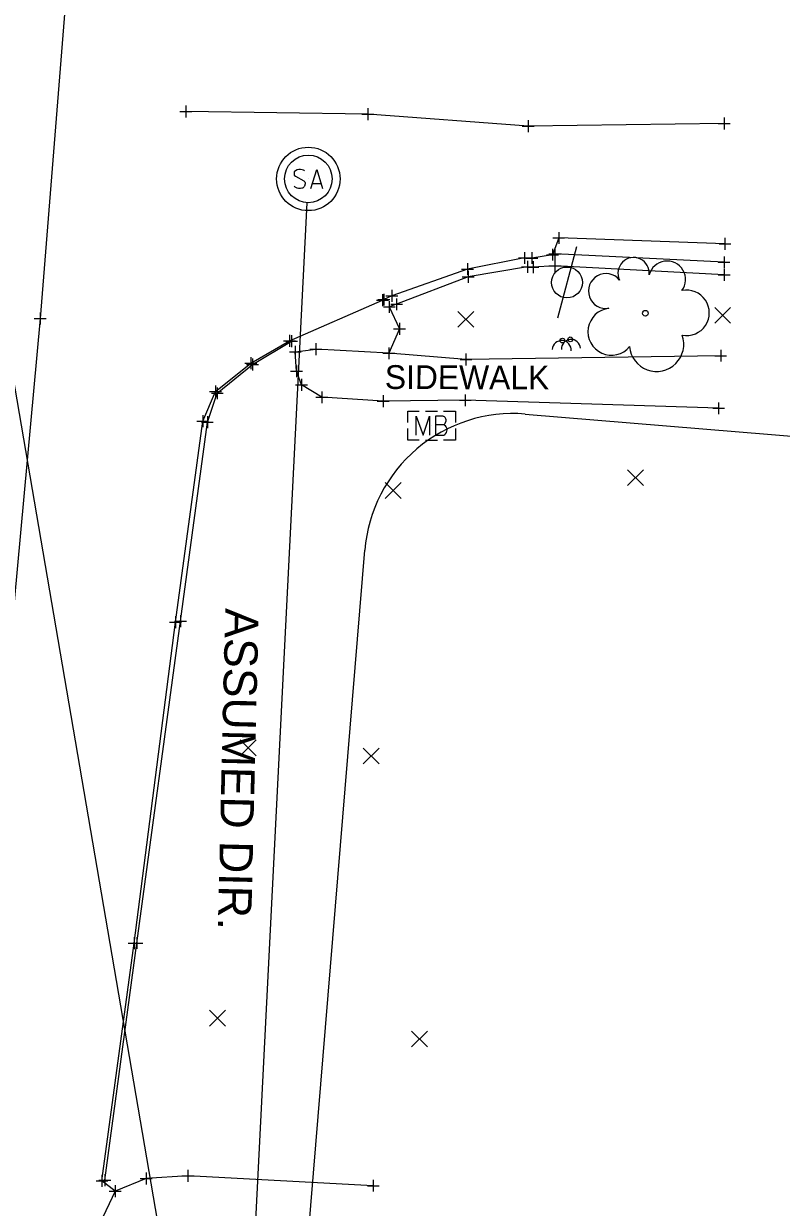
# Model space of a CAD drawing. Extents: x 1380550 to 1381945, y 468927 to 470496.
# Drawn here: x 1381528.9 to 1381592.6, y 469059.1 to 469158.5 of the extents above; entities that cross this region are included whole.
import ezdxf

# ---------------------------------------------------------------- set-up
doc = ezdxf.new("R2010")
doc.units = 0
for name, color, linetype in [('DR_X_Storm_Sewer', 7, 'Continuous'), ('DR_X_Text', 7, 'Continuous'), ('GK_Drainage_Nodes', 7, 'Continuous'), ('PV_X_COP', 7, 'Continuous'), ('PV_X_Curb', 7, 'Continuous'), ('PV_X_EOP', 7, 'Continuous'), ('PV_X_Walk', 7, 'Continuous'), ('RD_X_Cells', 7, 'Continuous'), ('RD_X_Text', 7, 'Continuous'), ('RW_X_Esmt_General', 7, 'Continuous'), ('SV_X_Random_Point', 7, 'Continuous'), ('SV_X_Shot_Marker', 7, 'Continuous'), ('UT_X_Electric', 7, 'Continuous'), ('UT_X_Misc_Cells', 7, 'Continuous'), ('UT_X_Sanitary_Cells', 7, 'Continuous'), ('UT_X_Telecom', 7, 'Continuous'), ('UT_X_Unknown_Cells', 7, 'Continuous'), ('VG_X_Cells', 7, 'Continuous')]:
    doc.layers.add(name, color=color, linetype=linetype)

msp = doc.modelspace()

# ---------------------------------------------------------------- linework, layer by layer
at = {"layer": 'DR_X_Storm_Sewer'}
msp.add_line((1381547.665, 469042.333), (1381552.759, 469143.476), dxfattribs=at)
at = {"layer": 'GK_Drainage_Nodes'}
for p, q in [((1381552.86, 469147.474), (1381552.86, 469147.474)), ((1381552.86, 469145.474), (1381552.86, 469145.474)), ((1381552.86, 469145.474), (1381552.86, 469145.474)), ((1381552.86, 469145.474), (1381552.86, 469145.474)), ((1381552.86, 469143.474), (1381552.86, 469143.474))]:
    msp.add_line(p, q, dxfattribs=at)
msp.add_circle((1381552.86, 469145.474), 2, dxfattribs=at)
at = {"layer": 'PV_X_COP'}
for points in [[(1381585.986, 469815.579), (1381581.288, 469760.779), (1381580.3, 469747.86), (1381578.724, 469729.445), (1381576.782, 469708.953), (1381575.288, 469689.792), (1381572.756, 469657.561), (1381569.364, 469615.703), (1381565.36, 469567.235), (1381561.161, 469537.516), (1381558.939, 469486.814), (1381555.385, 469442.034), (1381550.974, 469391.016), (1381547.282, 469345.901), (1381541.953, 469289.547), (1381537.187, 469231.269), (1381533.052, 469168.087), (1381530.317, 469133.741), (1381523.968, 469065.081), (1381520.119, 469021.37), (1381518.183, 469001.306)], [(1381587.818, 469150.124), (1381571.348, 469149.904), (1381557.859, 469150.909), (1381542.564, 469151.138)]]:
    msp.add_lwpolyline(points, dxfattribs=at)
at = {"layer": 'PV_X_Curb'}
for points in [[(1381587.812, 469138.466), (1381573.591, 469139.185), (1381573.393, 469139.107)], [(1381587.828, 469137.41), (1381573.578, 469138.171), (1381571.753, 469138.061), (1381571.295, 469138.094), (1381566.299, 469137.247), (1381560.284, 469134.94), (1381559.669, 469134.714)]]:
    msp.add_lwpolyline(points, dxfattribs=at)
at = {"layer": 'PV_X_EOP'}
for points in [[(1381587.891, 469140.014), (1381573.909, 469140.511), (1381573.393, 469139.107), (1381571.66, 469138.829), (1381571.03, 469138.831), (1381566.24, 469137.904), (1381559.875, 469135.65), (1381559.212, 469135.332)], [(1381558.323, 469060.888), (1381542.737, 469061.712), (1381539.218, 469061.498), (1381536.628, 469060.419), (1381535.511, 469061.291), (1381538.224, 469081.257), (1381541.702, 469108.24), (1381543.981, 469125.117), (1381545.062, 469127.608), (1381548.027, 469130.001), (1381551.277, 469131.879), (1381559.092, 469135.278)], [(1381559.669, 469134.714), (1381560.522, 469132.872), (1381559.627, 469130.822), (1381553.479, 469131.179)], [(1381535.753, 469061.359), (1381538.437, 469081.275), (1381542.11, 469108.32), (1381544.37, 469125.029), (1381545.209, 469127.461), (1381548.176, 469129.877), (1381551.456, 469131.851)], [(1381587.359, 469126.202), (1381566.057, 469126.873), (1381559.145, 469126.794), (1381553.992, 469127.124), (1381552.293, 469128.183), (1381551.861, 469129.31), (1381551.767, 469130.94), (1381553.479, 469131.179)], [(1381536.628, 469060.419), (1381535.328, 469057.717), (1381532.592, 469035.004), (1381532.732, 469034.306)]]:
    msp.add_lwpolyline(points, dxfattribs=at)
at = {"layer": 'PV_X_Walk'}
for points in [[(1381587.359, 469126.202), (1381566.057, 469126.873), (1381559.145, 469126.794), (1381553.992, 469127.124), (1381552.293, 469128.183), (1381551.861, 469129.31), (1381551.767, 469130.94), (1381553.479, 469131.179)], [(1381587.531, 469130.624), (1381566.113, 469130.294), (1381559.627, 469130.822), (1381553.479, 469131.179)]]:
    msp.add_lwpolyline(points, dxfattribs=at)
at = {"layer": 'RD_X_Cells'}
for p, q in [((1381562.71, 469125.969), (1381563.712, 469125.969)), ((1381563.222, 469124.747), (1381563.222, 469124.747)), ((1381562.71, 469123.526), (1381563.712, 469123.526))]:
    msp.add_line(p, q, dxfattribs=at)
for points in [[(1381561.222, 469124.999), (1381561.222, 469125.969), (1381562.192, 469125.969)], [(1381561.926, 469123.947), (1381561.926, 469125.547), (1381562.505, 469123.947), (1381563.059, 469125.547), (1381563.059, 469123.947)], [(1381564.244, 469124.817), (1381564.307, 469124.88), (1381564.345, 469124.918), (1381564.37, 469124.955), (1381564.382, 469124.98), (1381564.407, 469125.031), (1381564.42, 469125.069), (1381564.445, 469125.157), (1381564.445, 469125.195), (1381564.445, 469125.245), (1381564.433, 469125.321), (1381564.407, 469125.384), (1381564.37, 469125.434), (1381564.307, 469125.484), (1381564.256, 469125.51), (1381564.231, 469125.522), (1381564.168, 469125.547), (1381563.551, 469125.547), (1381563.551, 469123.947), (1381564.244, 469123.947), (1381564.332, 469123.998), (1381564.407, 469124.061), (1381564.47, 469124.162), (1381564.508, 469124.275), (1381564.521, 469124.388), (1381564.521, 469124.464), (1381564.496, 469124.54), (1381564.445, 469124.653), (1381564.382, 469124.728), (1381564.244, 469124.817), (1381563.551, 469124.817)], [(1381564.229, 469125.969), (1381565.222, 469125.969), (1381565.222, 469124.999)], [(1381562.192, 469123.526), (1381561.222, 469123.526), (1381561.222, 469124.496)], [(1381565.222, 469124.496), (1381565.222, 469123.526), (1381564.229, 469123.526)]]:
    msp.add_lwpolyline(points, dxfattribs=at)
at = {"layer": 'RW_X_Esmt_General'}
for p, q in [((1381571.101, 469125.715), (1381598.876, 469123.42)), ((1381550.441, 469027.475), (1381557.614, 469114.287))]:
    msp.add_line(p, q, dxfattribs=at)
msp.add_arc((1381570.071, 469113.258), 12.5, 85.27609, 175.27609, dxfattribs=at)
at = {"layer": 'SV_X_Random_Point'}
for p, q in [((1381565.433, 469133.008), (1381566.767, 469134.343)), ((1381565.433, 469134.343), (1381566.767, 469133.008)), ((1381587.033, 469133.342), (1381588.367, 469134.677)), ((1381587.033, 469134.677), (1381588.367, 469133.342)), ((1381579.697, 469119.709), (1381581.031, 469121.044)), ((1381579.697, 469121.044), (1381581.031, 469119.709)), ((1381559.325, 469118.625), (1381560.659, 469119.96)), ((1381559.325, 469119.96), (1381560.659, 469118.625)), ((1381547.143, 469097.003), (1381548.477, 469098.338)), ((1381547.143, 469098.338), (1381548.477, 469097.003)), ((1381557.485, 469096.319), (1381558.819, 469097.654)), ((1381557.485, 469097.654), (1381558.819, 469096.319)), ((1381544.559, 469074.296), (1381545.893, 469075.631)), ((1381544.559, 469075.631), (1381545.893, 469074.296)), ((1381561.532, 469072.541), (1381562.866, 469073.876)), ((1381561.532, 469073.876), (1381562.866, 469072.541))]:
    msp.add_line(p, q, dxfattribs=at)
at = {"layer": 'SV_X_Shot_Marker'}
for p, q in [((1381542.064, 469151.138), (1381543.064, 469151.138)), ((1381542.564, 469151.638), (1381542.564, 469150.638)), ((1381542.564, 469151.138), (1381542.564, 469151.138)), ((1381557.859, 469151.409), (1381557.859, 469150.409)), ((1381557.359, 469150.909), (1381558.359, 469150.909)), ((1381557.859, 469150.909), (1381557.859, 469150.909)), ((1381571.348, 469150.404), (1381571.348, 469149.404)), ((1381587.318, 469150.124), (1381588.318, 469150.124)), ((1381587.818, 469150.624), (1381587.818, 469149.624)), ((1381587.818, 469150.124), (1381587.818, 469150.124)), ((1381570.848, 469149.904), (1381571.848, 469149.904)), ((1381571.348, 469149.904), (1381571.348, 469149.904)), ((1381573.909, 469141.011), (1381573.909, 469140.011)), ((1381573.409, 469140.511), (1381574.409, 469140.511)), ((1381573.909, 469140.511), (1381573.909, 469140.511)), ((1381587.391, 469140.014), (1381588.391, 469140.014)), ((1381587.891, 469140.514), (1381587.891, 469139.514)), ((1381587.891, 469140.014), (1381587.891, 469140.014)), ((1381571.03, 469139.331), (1381571.03, 469138.331)), ((1381571.03, 469139.331), (1381571.03, 469138.331)), ((1381571.66, 469139.329), (1381571.66, 469138.329)), ((1381572.893, 469139.107), (1381573.893, 469139.107)), ((1381572.893, 469139.107), (1381573.893, 469139.107)), ((1381573.091, 469139.185), (1381574.091, 469139.185)), ((1381573.393, 469139.607), (1381573.393, 469138.607)), ((1381573.393, 469139.607), (1381573.393, 469138.607)), ((1381573.393, 469139.107), (1381573.393, 469139.107)), ((1381573.393, 469139.107), (1381573.393, 469139.107)), ((1381573.591, 469139.685), (1381573.591, 469138.685)), ((1381573.591, 469139.185), (1381573.591, 469139.185)), ((1381566.24, 469138.404), (1381566.24, 469137.404)), ((1381570.53, 469138.831), (1381571.53, 469138.831)), ((1381570.53, 469138.831), (1381571.53, 469138.831)), ((1381570.795, 469138.094), (1381571.795, 469138.094)), ((1381570.795, 469138.094), (1381571.795, 469138.094)), ((1381571.03, 469138.831), (1381571.03, 469138.831)), ((1381571.03, 469138.831), (1381571.03, 469138.831)), ((1381571.16, 469138.829), (1381572.16, 469138.829)), ((1381571.253, 469138.061), (1381572.253, 469138.061)), ((1381571.295, 469138.594), (1381571.295, 469137.594)), ((1381571.295, 469138.594), (1381571.295, 469137.594)), ((1381571.295, 469138.094), (1381571.295, 469138.094)), ((1381571.295, 469138.094), (1381571.295, 469138.094)), ((1381571.66, 469138.829), (1381571.66, 469138.829)), ((1381571.753, 469138.561), (1381571.753, 469137.561)), ((1381571.753, 469138.061), (1381571.753, 469138.061)), ((1381573.078, 469138.171), (1381574.078, 469138.171)), ((1381573.578, 469138.671), (1381573.578, 469137.671)), ((1381573.578, 469138.171), (1381573.578, 469138.171)), ((1381587.312, 469138.466), (1381588.312, 469138.466)), ((1381587.812, 469138.966), (1381587.812, 469137.966)), ((1381587.812, 469138.466), (1381587.812, 469138.466)), ((1381565.74, 469137.904), (1381566.74, 469137.904)), ((1381565.799, 469137.247), (1381566.799, 469137.247)), ((1381566.24, 469137.904), (1381566.24, 469137.904)), ((1381566.299, 469137.747), (1381566.299, 469136.747)), ((1381566.299, 469137.247), (1381566.299, 469137.247)), ((1381587.328, 469137.41), (1381588.328, 469137.41)), ((1381587.828, 469137.91), (1381587.828, 469136.91)), ((1381587.828, 469137.41), (1381587.828, 469137.41)), ((1381559.875, 469136.15), (1381559.875, 469135.15)), ((1381559.875, 469136.15), (1381559.875, 469135.15)), ((1381558.592, 469135.278), (1381559.592, 469135.278)), ((1381558.712, 469135.332), (1381559.712, 469135.332)), ((1381559.092, 469135.778), (1381559.092, 469134.778)), ((1381559.092, 469135.278), (1381559.092, 469135.278)), ((1381559.212, 469135.832), (1381559.212, 469134.832)), ((1381559.212, 469135.332), (1381559.212, 469135.332)), ((1381559.375, 469135.65), (1381560.375, 469135.65)), ((1381559.375, 469135.65), (1381560.375, 469135.65)), ((1381559.669, 469135.214), (1381559.669, 469134.214)), ((1381559.669, 469135.214), (1381559.669, 469134.214)), ((1381559.875, 469135.65), (1381559.875, 469135.65)), ((1381559.875, 469135.65), (1381559.875, 469135.65)), ((1381560.284, 469135.44), (1381560.284, 469134.44)), ((1381560.284, 469135.44), (1381560.284, 469134.44)), ((1381530.317, 469134.241), (1381530.317, 469133.241)), ((1381559.169, 469134.714), (1381560.169, 469134.714)), ((1381559.169, 469134.714), (1381560.169, 469134.714)), ((1381559.669, 469134.714), (1381559.669, 469134.714)), ((1381559.669, 469134.714), (1381559.669, 469134.714)), ((1381559.784, 469134.94), (1381560.784, 469134.94)), ((1381559.784, 469134.94), (1381560.784, 469134.94)), ((1381560.284, 469134.94), (1381560.284, 469134.94)), ((1381560.284, 469134.94), (1381560.284, 469134.94)), ((1381529.817, 469133.741), (1381530.817, 469133.741)), ((1381530.317, 469133.741), (1381530.317, 469133.741)), ((1381560.522, 469133.372), (1381560.522, 469132.372)), ((1381551.277, 469132.379), (1381551.277, 469131.379)), ((1381551.456, 469132.351), (1381551.456, 469131.351)), ((1381560.022, 469132.872), (1381561.022, 469132.872)), ((1381560.522, 469132.872), (1381560.522, 469132.872)), ((1381550.777, 469131.879), (1381551.777, 469131.879)), ((1381550.956, 469131.851), (1381551.956, 469131.851)), ((1381551.277, 469131.879), (1381551.277, 469131.879)), ((1381551.456, 469131.851), (1381551.456, 469131.851)), ((1381551.767, 469131.44), (1381551.767, 469130.44)), ((1381551.767, 469131.44), (1381551.767, 469130.44)), ((1381552.979, 469131.179), (1381553.979, 469131.179)), ((1381552.979, 469131.179), (1381553.979, 469131.179)), ((1381552.979, 469131.179), (1381553.979, 469131.179)), ((1381552.979, 469131.179), (1381553.979, 469131.179)), ((1381553.479, 469131.679), (1381553.479, 469130.679)), ((1381553.479, 469131.679), (1381553.479, 469130.679)), ((1381553.479, 469131.679), (1381553.479, 469130.679)), ((1381553.479, 469131.679), (1381553.479, 469130.679)), ((1381553.479, 469131.179), (1381553.479, 469131.179)), ((1381553.479, 469131.179), (1381553.479, 469131.179)), ((1381553.479, 469131.179), (1381553.479, 469131.179)), ((1381553.479, 469131.179), (1381553.479, 469131.179)), ((1381559.627, 469131.322), (1381559.627, 469130.322)), ((1381559.627, 469131.322), (1381559.627, 469130.322)), ((1381587.531, 469131.124), (1381587.531, 469130.124)), ((1381548.027, 469130.501), (1381548.027, 469129.501)), ((1381548.176, 469130.377), (1381548.176, 469129.377)), ((1381551.267, 469130.94), (1381552.267, 469130.94)), ((1381551.267, 469130.94), (1381552.267, 469130.94)), ((1381551.767, 469130.94), (1381551.767, 469130.94)), ((1381551.767, 469130.94), (1381551.767, 469130.94)), ((1381559.127, 469130.822), (1381560.127, 469130.822)), ((1381559.127, 469130.822), (1381560.127, 469130.822)), ((1381559.627, 469130.822), (1381559.627, 469130.822)), ((1381559.627, 469130.822), (1381559.627, 469130.822)), ((1381565.613, 469130.294), (1381566.613, 469130.294)), ((1381566.113, 469130.794), (1381566.113, 469129.794)), ((1381566.113, 469130.294), (1381566.113, 469130.294)), ((1381587.031, 469130.624), (1381588.031, 469130.624)), ((1381587.531, 469130.624), (1381587.531, 469130.624)), ((1381547.527, 469130.001), (1381548.527, 469130.001)), ((1381547.676, 469129.877), (1381548.676, 469129.877)), ((1381548.027, 469130.001), (1381548.027, 469130.001)), ((1381548.176, 469129.877), (1381548.176, 469129.877)), ((1381551.361, 469129.31), (1381552.361, 469129.31)), ((1381551.361, 469129.31), (1381552.361, 469129.31)), ((1381551.861, 469129.81), (1381551.861, 469128.81)), ((1381551.861, 469129.81), (1381551.861, 469128.81)), ((1381551.861, 469129.31), (1381551.861, 469129.31)), ((1381551.861, 469129.31), (1381551.861, 469129.31)), ((1381545.062, 469128.108), (1381545.062, 469127.108)), ((1381551.793, 469128.183), (1381552.793, 469128.183)), ((1381551.793, 469128.183), (1381552.793, 469128.183)), ((1381552.293, 469128.683), (1381552.293, 469127.683)), ((1381552.293, 469128.683), (1381552.293, 469127.683)), ((1381552.293, 469128.183), (1381552.293, 469128.183)), ((1381552.293, 469128.183), (1381552.293, 469128.183)), ((1381544.562, 469127.608), (1381545.562, 469127.608)), ((1381544.709, 469127.461), (1381545.709, 469127.461)), ((1381545.062, 469127.608), (1381545.062, 469127.608)), ((1381545.209, 469127.961), (1381545.209, 469126.961)), ((1381545.209, 469127.461), (1381545.209, 469127.461)), ((1381553.492, 469127.124), (1381554.492, 469127.124)), ((1381553.492, 469127.124), (1381554.492, 469127.124)), ((1381553.992, 469127.624), (1381553.992, 469126.624)), ((1381553.992, 469127.624), (1381553.992, 469126.624)), ((1381553.992, 469127.124), (1381553.992, 469127.124)), ((1381553.992, 469127.124), (1381553.992, 469127.124)), ((1381559.145, 469127.294), (1381559.145, 469126.294)), ((1381559.145, 469127.294), (1381559.145, 469126.294)), ((1381566.057, 469127.373), (1381566.057, 469126.373)), ((1381566.057, 469127.373), (1381566.057, 469126.373)), ((1381558.645, 469126.794), (1381559.645, 469126.794)), ((1381558.645, 469126.794), (1381559.645, 469126.794)), ((1381559.145, 469126.794), (1381559.145, 469126.794)), ((1381559.145, 469126.794), (1381559.145, 469126.794)), ((1381565.557, 469126.873), (1381566.557, 469126.873)), ((1381565.557, 469126.873), (1381566.557, 469126.873)), ((1381566.057, 469126.873), (1381566.057, 469126.873)), ((1381566.057, 469126.873), (1381566.057, 469126.873)), ((1381586.859, 469126.202), (1381587.859, 469126.202)), ((1381586.859, 469126.202), (1381587.859, 469126.202)), ((1381587.359, 469126.702), (1381587.359, 469125.702)), ((1381587.359, 469126.702), (1381587.359, 469125.702)), ((1381587.359, 469126.202), (1381587.359, 469126.202)), ((1381587.359, 469126.202), (1381587.359, 469126.202)), ((1381543.481, 469125.117), (1381544.481, 469125.117)), ((1381543.981, 469125.617), (1381543.981, 469124.617)), ((1381543.981, 469125.117), (1381543.981, 469125.117)), ((1381544.37, 469125.529), (1381544.37, 469124.529)), ((1381543.87, 469125.029), (1381544.87, 469125.029)), ((1381544.37, 469125.029), (1381544.37, 469125.029)), ((1381541.202, 469108.24), (1381542.202, 469108.24)), ((1381541.61, 469108.32), (1381542.61, 469108.32)), ((1381541.702, 469108.74), (1381541.702, 469107.74)), ((1381541.702, 469108.24), (1381541.702, 469108.24)), ((1381542.11, 469108.82), (1381542.11, 469107.82)), ((1381542.11, 469108.32), (1381542.11, 469108.32)), ((1381538.224, 469081.757), (1381538.224, 469080.757)), ((1381538.437, 469081.775), (1381538.437, 469080.775)), ((1381537.724, 469081.257), (1381538.724, 469081.257)), ((1381537.937, 469081.275), (1381538.937, 469081.275)), ((1381538.224, 469081.257), (1381538.224, 469081.257)), ((1381538.437, 469081.275), (1381538.437, 469081.275)), ((1381535.511, 469061.791), (1381535.511, 469060.791)), ((1381535.753, 469061.859), (1381535.753, 469060.859)), ((1381538.718, 469061.498), (1381539.718, 469061.498)), ((1381539.218, 469061.998), (1381539.218, 469060.998)), ((1381539.218, 469061.498), (1381539.218, 469061.498)), ((1381542.237, 469061.712), (1381543.237, 469061.712)), ((1381542.737, 469062.212), (1381542.737, 469061.212)), ((1381542.737, 469061.712), (1381542.737, 469061.712)), ((1381535.011, 469061.291), (1381536.011, 469061.291)), ((1381535.253, 469061.359), (1381536.253, 469061.359)), ((1381535.511, 469061.291), (1381535.511, 469061.291)), ((1381535.753, 469061.359), (1381535.753, 469061.359)), ((1381536.628, 469060.919), (1381536.628, 469059.919)), ((1381536.628, 469060.919), (1381536.628, 469059.919)), ((1381557.823, 469060.888), (1381558.823, 469060.888)), ((1381558.323, 469061.388), (1381558.323, 469060.388)), ((1381558.323, 469060.888), (1381558.323, 469060.888)), ((1381536.128, 469060.419), (1381537.128, 469060.419)), ((1381536.128, 469060.419), (1381537.128, 469060.419)), ((1381536.628, 469060.419), (1381536.628, 469060.419)), ((1381536.628, 469060.419), (1381536.628, 469060.419))]:
    msp.add_line(p, q, dxfattribs=at)
at = {"layer": 'UT_X_Electric'}
msp.add_lwpolyline([(1381665.562, 470247.404), (1381595.795, 470220.833), (1381581.264, 470018.199), (1381571.968, 469887.64), (1381559.775, 469757.408), (1381543.86, 469565.781), (1381529.165, 469390.12), (1381515.279, 469203.101), (1381540.8, 469054.263)], dxfattribs=at)
at = {"layer": 'UT_X_Misc_Cells'}
for centre in [(1381574.224, 469131.89), (1381574.888, 469131.993)]:
    msp.add_circle(centre, 0.2, dxfattribs=at)
for centre, start, end in [((1381574.161, 469131.092), 355.50341, 175.50341), ((1381574.935, 469131.194), 3.35255, 183.35255)]:
    msp.add_arc(centre, 0.8, start, end, dxfattribs=at)
at = {"layer": 'UT_X_Sanitary_Cells'}
for points in [[(1381552.527, 469146.16), (1381552.502, 469146.186), (1381552.464, 469146.211), (1381552.351, 469146.249), (1381552.212, 469146.274), (1381552.112, 469146.274), (1381552.074, 469146.274), (1381551.91, 469146.236), (1381551.772, 469146.16), (1381551.683, 469146.06), (1381551.658, 469145.959), (1381551.658, 469145.883), (1381551.683, 469145.782), (1381551.784, 469145.694), (1381552.477, 469145.316), (1381552.54, 469145.266), (1381552.565, 469145.216), (1381552.59, 469145.14), (1381552.59, 469145.065), (1381552.578, 469144.989), (1381552.565, 469144.939), (1381552.54, 469144.875), (1381552.515, 469144.825), (1381552.49, 469144.787), (1381552.452, 469144.749), (1381552.414, 469144.724), (1381552.364, 469144.699), (1381552.326, 469144.687), (1381552.212, 469144.674), (1381552.036, 469144.674), (1381551.923, 469144.699), (1381551.759, 469144.787), (1381551.658, 469144.863)], [(1381553.069, 469144.674), (1381553.573, 469146.274), (1381554.064, 469144.674)], [(1381553.938, 469145.052), (1381553.195, 469145.052)]]:
    msp.add_lwpolyline(points, dxfattribs=at)
for radius in [2.667, 2]:
    msp.add_circle((1381552.86, 469145.474), radius, dxfattribs=at)
at = {"layer": 'UT_X_Telecom'}
msp.add_lwpolyline([(1381665.562, 470247.404), (1381595.346, 470217.51), (1381581.264, 470018.199), (1381571.968, 469887.64), (1381559.775, 469757.408), (1381543.86, 469565.781), (1381529.165, 469390.12), (1381515.279, 469203.101), (1381540.8, 469054.263)], dxfattribs=at)
at = {"layer": 'UT_X_Unknown_Cells'}
msp.add_line((1381575.411, 469139.773), (1381573.805, 469133.773), dxfattribs=at)
msp.add_circle((1381574.608, 469136.773), 1.3, dxfattribs=at)
at = {"layer": 'VG_X_Cells'}
msp.add_circle((1381581.196, 469134.188), 0.24, dxfattribs=at)
for centre, radius, start, end in [((1381580.212, 469137.555), 1.317, 354.0047, 205.97412), ((1381583.022, 469137.017), 1.553, 323.82996, 165.0376), ((1381577.887, 469136.052), 1.471, 39.06254, 279.54124), ((1381584.656, 469134.224), 1.915, 259.14531, 101.45961), ((1381578.343, 469132.639), 1.974, 96.17219, 320.57371), ((1381582.142, 469131.583), 2.284, 184.94757, 19.45715)]:
    msp.add_arc(centre, radius, start, end, dxfattribs=at)

# ---------------------------------------------------------------- texts
at = {"layer": 'DR_X_Text'}
msp.add_text('ASSUMED DIR.', height=2.8, rotation=268.65705, dxfattribs=at).set_placement((1381545.881, 469109.421))
at = {"layer": 'RD_X_Text'}
msp.add_text('SIDEWALK', height=2, rotation=359.81862, dxfattribs=at).set_placement((1381559.292, 469127.828))

doc.saveas('drawing.dxf')
